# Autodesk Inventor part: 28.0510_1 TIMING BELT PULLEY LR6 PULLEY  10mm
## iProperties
Created: 2007-06
Part Number: 28.0510_1 TIMING BELT PULLEY LR6 PULLEY  10mm
Document SubType Name: Modeling
Designer: Andy Moles
Material: Aluminum-6061
Density: 2.71 g/cm^3
Mass: 134.176 g
Surface Area: 166.875 cm^2
Volume: 49.5115 cm^3
Author: Andy Moles
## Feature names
1. Revolution1
2. Extrusion1
3. Circular Pattern1
4. Extrusion2
5. Mirror1
6. Extrusion3
7. Chamfer1
